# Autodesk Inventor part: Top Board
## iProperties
Created: 2010-08
Part Number: Top Board
Material: Default
Document SubType Name: Modeling
Designer: Paul Munford
Density: 1 g/cm^3
Author: Paul Munford
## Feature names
1. TaggingFeature2
